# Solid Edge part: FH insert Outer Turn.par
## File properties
Author: Dan
Template: FH Insert .par
Last saved by: Dan
Revision: 18
Application: Solid Edge
Density: 7833.000 kg/m^3
Accuracy: 0.990
Material: Steel
Face Style: Steel
Fill Style: ANSI32(Steel)
Virtual Style: Machined steel
Coef. of Thermal Exp: 1.3e-05
Thermal Conductivity: 32.0
Specific Heat: 481.0
Modulus of Elasticity: 199947953000.0
Poisson's Ratio: 0.29
Yield Stress: 262000766.0
Ultimate Stress: 358527364.0
Elongation: 0.0
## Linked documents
FH Insert .par
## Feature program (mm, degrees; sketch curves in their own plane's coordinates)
part copy "CopiedPart_1"
sketch for "ExtrudedCutout_1" plane through (0, 0, -36) normal (0, 0, -1) x-axis (-1, 0, 0)
  circle centre (0, 0) radius 22.25
extrude "ExtrudedCutout_1" cut finite 5.03 along -normal
sketch for "Hole_5" plane through (0, 0, -36) normal (0, 0, -1) x-axis (-1, 0, 0)
  hole centre (-39.8448, 16.1322) bore radius 2.4585
hole "Hole_5" finite
sketch for "unnamed Hole 1" plane through (0, 0, -36) normal (0, 0, -1) x-axis (-1, 0, 0)
hole "unnamed Hole 1" finite
sketch for "unnamed Hole 2" plane through (0, 0, -36) normal (0, 0, -1) x-axis (-1, 0, 0)
  hole centre (16.1322, 39.893) bore radius 2.4585
hole "unnamed Hole 2" finite
sketch for "unnamed Hole 3" plane through (0, 0, -36) normal (0, 0, -1) x-axis (-1, 0, 0)
  hole centre (39.893, -16.084) bore radius 2.4585
hole "unnamed Hole 3" finite
pattern "unnamed Pattern 1" of "Hole_5", "unnamed Hole 1", "unnamed Hole 2", "unnamed Hole 3"
delete holes assoc c "unnamed DeleteHolesAssocC 1"
sketch for "unnamed RevolvedProtrusion 1" plane through (0, 0, 0) normal (1, 0, 0) x-axis (0, 1, 0)
revolve "unnamed RevolvedProtrusion 1" add full turn 360 deg
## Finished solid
Body 1: solid body, 30 faces, 30 edges, 4 vertices.
  Faces by surface: cylinder 13, plane 13, torus 2, cone 1, spun 1
  Edges by curve: circle 30
Bounding box of the edges (mm; curved faces can reach further): 116.000 x 116.000 x 26.842, from (-58, -58, -36) to (58, 58, -9.1581).
Cylindrical faces by radius (mm): R18.8116 x1, R21.8198 x1, R22.25 x1, R26.8948 x1, R35.25 x1, R41.25 x1, R53 x1, R55.65 x2, R58 x4
Conical faces (half-angle, radius in mm at the cone's reference point): 2 deg R19.3388 x1
Toroidal faces (ring radius, tube radius in mm): R20.4107 r1.015 x1, R38.25 r3 x1
Planar faces by outward normal: +z 8, -z 5
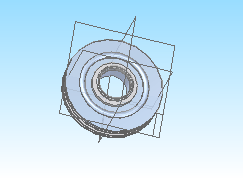
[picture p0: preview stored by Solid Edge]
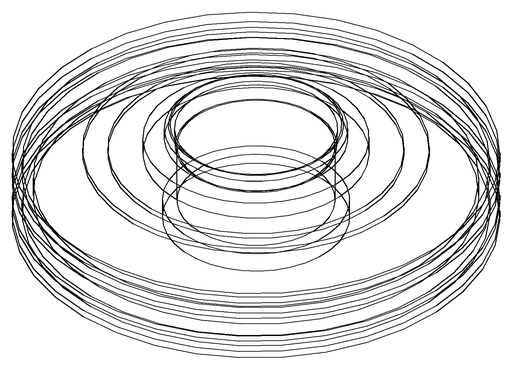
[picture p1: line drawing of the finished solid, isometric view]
